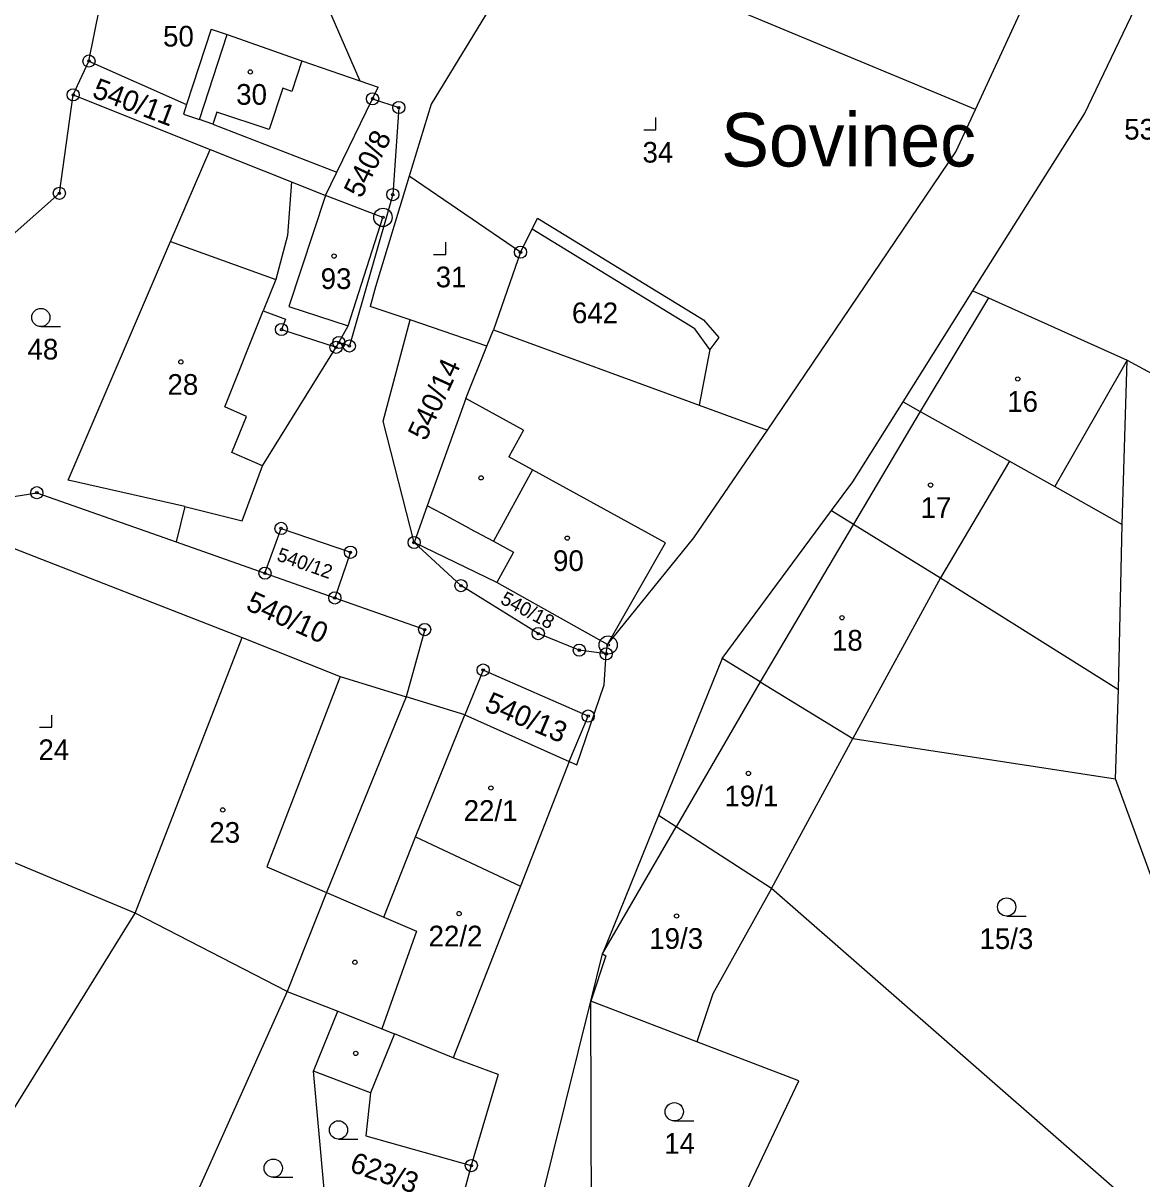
# Model space of a CAD drawing. Extents: x -547623 to -538651, y -1096714 to -1086522.
# Drawn here: x -544855 to -544763.1, y -1094700.8 to -1094605.9 of the extents above; entities that cross this region are included whole.
import ezdxf

# ---------------------------------------------------------------- set-up
doc = ezdxf.new("R2010")
doc.units = 0
for name, color, linetype in [('Vrstva 1', 7, 'Continuous'), ('Vrstva 25', 7, 'Continuous'), ('Vrstva 30', 7, 'Continuous'), ('Vrstva 33', 7, 'Continuous'), ('Vrstva 50', 7, 'Continuous'), ('Vrstva 83', 7, 'Continuous'), ('Vrstva 86', 7, 'Continuous'), ('Vrstva 90', 7, 'Continuous'), ('Vrstva 92', 7, 'Continuous')]:
    doc.layers.add(name, color=color, linetype=linetype)

msp = doc.modelspace()

# ---------------------------------------------------------------- linework, layer by layer
at = {"layer": 'Vrstva 1'}
for points in [[(-544767.78, -1094613.32), (-544755.08, -1094586.85)], [(-544812.58, -1094598.01), (-544821.44, -1094612.52)], [(-544782.68, -1094610.49), (-544812.58, -1094598.01)], [(-544776.73, -1094612.97), (-544769.76, -1094597.88)], [(-544849.55, -1094608.99), (-544847.75, -1094600.04)], [(-544830.34, -1094603.61), (-544827.31, -1094610.61)], [(-544839.52, -1094606.36), (-544841.53, -1094612.57)], [(-544839.52, -1094606.36), (-544838.2, -1094606.82)], [(-544838.2, -1094606.82), (-544832.05, -1094608.96)], [(-544850.84, -1094611.77), (-544849.55, -1094608.99)], [(-544849.55, -1094608.99), (-544841.53, -1094612.57)], [(-544832.05, -1094608.96), (-544827.31, -1094610.61)], [(-544827.31, -1094610.61), (-544825.79, -1094611.14)], [(-544776.73, -1094612.97), (-544782.68, -1094610.49)], [(-544851.98, -1094619.85), (-544850.84, -1094611.77)], [(-544850.84, -1094611.77), (-544839.6, -1094616.25)], [(-544826.25, -1094612.09), (-544825.79, -1094611.14)], [(-544841.53, -1094612.57), (-544841.78, -1094613.34)], [(-544829.18, -1094618.11), (-544826.25, -1094612.09)], [(-544826.25, -1094612.09), (-544824.1, -1094612.81)], [(-544824.1, -1094612.81), (-544824.59, -1094619.96)], [(-544821.44, -1094612.52), (-544823.25, -1094618.45)], [(-544841.78, -1094613.34), (-544840.46, -1094613.8)], [(-544839.37, -1094614.17), (-544840.46, -1094613.8)], [(-544778.33, -1094616.44), (-544776.73, -1094612.97)], [(-544776.93, -1094627.86), (-544767.78, -1094613.32)], [(-544839.37, -1094614.17), (-544829.18, -1094618.11)], [(-544842.85, -1094623.81), (-544839.6, -1094616.25)], [(-544839.6, -1094616.25), (-544832.92, -1094618.91)], [(-544793.8, -1094639.31), (-544778.33, -1094616.44)], [(-544830.11, -1094620.03), (-544829.18, -1094618.11)], [(-544823.25, -1094618.45), (-544826.02, -1094627.54)], [(-544814.1, -1094624.69), (-544823.25, -1094618.45)], [(-544832.92, -1094618.91), (-544833.25, -1094623.32)], [(-544832.92, -1094618.91), (-544830.11, -1094620.03)], [(-544855.87, -1094623.28), (-544851.98, -1094619.85)], [(-544825.41, -1094621.84), (-544830.11, -1094620.03)], [(-544824.59, -1094619.96), (-544828.16, -1094632.39)], [(-544828.26, -1094630.73), (-544825.41, -1094621.84)], [(-544813.15, -1094622.79), (-544812.7, -1094621.89)], [(-544812.7, -1094621.89), (-544799.08, -1094630.24)], [(-544833.25, -1094623.32), (-544834.19, -1094626.93)], [(-544814.1, -1094624.69), (-544813.15, -1094622.79)], [(-544851.26, -1094643.41), (-544842.85, -1094623.81)], [(-544814.1, -1094624.69), (-544816.33, -1094631.06)], [(-544834.19, -1094626.93), (-544835.23, -1094629.51)], [(-544826.02, -1094627.54), (-544826.46, -1094629.16)], [(-544782.67, -1094636.98), (-544776.93, -1094627.86)], [(-544776.93, -1094627.86), (-544775.66, -1094628.43)], [(-544775.66, -1094628.43), (-544764.27, -1094633.56)], [(-544835.23, -1094629.51), (-544833.4, -1094630.2)], [(-544823.17, -1094630.25), (-544826.46, -1094629.16)], [(-544833.4, -1094630.2), (-544833.73, -1094631.04)], [(-544829.02, -1094632.11), (-544828.26, -1094630.73)], [(-544825.38, -1094638.57), (-544823.17, -1094630.25)], [(-544816.87, -1094632.4), (-544823.17, -1094630.25)], [(-544799.08, -1094630.24), (-544797.82, -1094631.68)], [(-544833.73, -1094631.04), (-544829.25, -1094632.5)], [(-544816.87, -1094632.4), (-544816.33, -1094631.06)], [(-544816.33, -1094631.06), (-544799.42, -1094637.25)], [(-544797.82, -1094631.68), (-544798.55, -1094632.67)], [(-544835.29, -1094642.23), (-544829.25, -1094632.5)], [(-544829.25, -1094632.5), (-544829.02, -1094632.11)], [(-544828.16, -1094632.39), (-544829.02, -1094632.11)], [(-544818.6, -1094636.69), (-544816.87, -1094632.4)], [(-544798.55, -1094632.67), (-544799.42, -1094637.25)], [(-544764.67, -1094647.05), (-544764.27, -1094633.56)], [(-544764.27, -1094633.56), (-544756.99, -1094637.51)], [(-544818.6, -1094636.69), (-544821.76, -1094645.51)], [(-544799.42, -1094637.25), (-544793.8, -1094639.31)], [(-544786.81, -1094643.54), (-544782.67, -1094636.98)], [(-544782.67, -1094636.98), (-544781.27, -1094637.76)], [(-544781.27, -1094637.76), (-544773.94, -1094641.86)], [(-544822.84, -1094648.53), (-544825.38, -1094638.57)], [(-544799.86, -1094648.14), (-544793.8, -1094639.31)], [(-544836.95, -1094646.74), (-544835.29, -1094642.23)], [(-544773.94, -1094641.86), (-544770.22, -1094643.94)], [(-544841.68, -1094645.57), (-544851.26, -1094643.41)], [(-544788.56, -1094645.91), (-544786.81, -1094643.54)], [(-544770.22, -1094643.94), (-544764.67, -1094647.05)], [(-544857.98, -1094645.11), (-544853.83, -1094644.44)], [(-544853.83, -1094644.44), (-544842.38, -1094648.48)], [(-544841.68, -1094645.57), (-544842.38, -1094648.48)], [(-544841.68, -1094645.57), (-544836.95, -1094646.74)], [(-544821.76, -1094645.51), (-544822.84, -1094648.53)], [(-544797.54, -1094658.05), (-544788.56, -1094645.91)], [(-544788.56, -1094645.91), (-544786.74, -1094647.03)], [(-544786.74, -1094647.03), (-544779.59, -1094651.43)], [(-544764.98, -1094660.59), (-544764.67, -1094647.05)], [(-544835.09, -1094651.05), (-544833.77, -1094647.37)], [(-544833.77, -1094647.37), (-544828.07, -1094649.33)], [(-544856.31, -1094648.77), (-544836.96, -1094656.32)], [(-544842.38, -1094648.48), (-544835.09, -1094651.05)], [(-544818.99, -1094652.07), (-544822.84, -1094648.53)], [(-544816.05, -1094651.81), (-544822.84, -1094648.53)], [(-544806.94, -1094656.91), (-544799.86, -1094648.14)], [(-544828.07, -1094649.33), (-544829.35, -1094653.08)], [(-544835.09, -1094651.05), (-544829.35, -1094653.08)], [(-544806.94, -1094656.91), (-544816.05, -1094651.81)], [(-544779.59, -1094651.43), (-544764.98, -1094660.59)], [(-544812.64, -1094656.01), (-544818.99, -1094652.07)], [(-544829.35, -1094653.08), (-544821.97, -1094655.68)], [(-544845.75, -1094678.98), (-544836.96, -1094656.32)], [(-544836.96, -1094656.32), (-544828.92, -1094659.53)], [(-544821.97, -1094655.68), (-544823.49, -1094661.19)], [(-544809.27, -1094657.37), (-544812.64, -1094656.01)], [(-544807.06, -1094657.67), (-544809.27, -1094657.37)], [(-544807.06, -1094657.67), (-544806.94, -1094656.91)], [(-544807.24, -1094660.23), (-544807.06, -1094657.67)], [(-544797.54, -1094658.05), (-544802.77, -1094670.95)], [(-544794.41, -1094659.97), (-544797.54, -1094658.05)], [(-544817.17, -1094659), (-544818.66, -1094662.69)], [(-544808.54, -1094662.78), (-544817.17, -1094659)], [(-544828.92, -1094659.53), (-544823.49, -1094661.19)], [(-544809.47, -1094666.78), (-544807.24, -1094660.23)], [(-544794.41, -1094659.97), (-544786.8, -1094664.63)], [(-544823.49, -1094661.19), (-544830.03, -1094677.28)], [(-544818.66, -1094662.69), (-544823.49, -1094661.19)], [(-544765.21, -1094667.93), (-544764.98, -1094660.59)], [(-544818.66, -1094662.69), (-544810.09, -1094666.51)], [(-544810.09, -1094666.51), (-544808.54, -1094662.78)], [(-544793.49, -1094676.93), (-544786.8, -1094664.63)], [(-544786.8, -1094664.63), (-544765.21, -1094667.93)], [(-544810.09, -1094666.51), (-544814.1, -1094676.75)], [(-544810.09, -1094666.51), (-544809.47, -1094666.78)], [(-544761.84, -1094677.22), (-544765.21, -1094667.93)], [(-544802.77, -1094670.95), (-544807.37, -1094682.31)], [(-544801.32, -1094671.88), (-544802.77, -1094670.95)], [(-544845.75, -1094678.98), (-544862.15, -1094672.13)], [(-544825.33, -1094679.3), (-544822.72, -1094672.7)], [(-544822.72, -1094672.7), (-544814.1, -1094676.75)], [(-544793.49, -1094676.93), (-544801.32, -1094671.88)], [(-544830.03, -1094677.28), (-544833.26, -1094685.41)], [(-544814.1, -1094676.75), (-544819.62, -1094690.84)], [(-544793.49, -1094676.93), (-544798.3, -1094685.58)], [(-544761.16, -1094705.2), (-544793.49, -1094676.93)], [(-544856.17, -1094695.74), (-544845.75, -1094678.98)], [(-544833.26, -1094685.41), (-544845.75, -1094678.98)], [(-544825.33, -1094679.3), (-544822.64, -1094680.45)], [(-544822.64, -1094680.45), (-544825.48, -1094688.48)], [(-544808.31, -1094686.2), (-544807.37, -1094682.31)], [(-544833.26, -1094685.41), (-544841.88, -1094704.64)], [(-544833.26, -1094685.41), (-544829.11, -1094687.02)], [(-544798.3, -1094685.58), (-544799.62, -1094689.53)], [(-544813.52, -1094707.15), (-544808.31, -1094686.2)], [(-544799.62, -1094689.53), (-544808.31, -1094686.2)], [(-544808.27, -1094704.24), (-544808.31, -1094686.2)], [(-544831.1, -1094691.95), (-544829.11, -1094687.02)], [(-544829.11, -1094687.02), (-544825.48, -1094688.48)], [(-544791.23, -1094692.75), (-544799.62, -1094689.53)], [(-544815.93, -1094692.21), (-544819.62, -1094690.84)], [(-544826.41, -1094693.73), (-544831.1, -1094691.95)], [(-544830.24, -1094701.64), (-544831.1, -1094691.95)], [(-544815.93, -1094692.21), (-544818.14, -1094699.7)], [(-544797.96, -1094706.94), (-544791.23, -1094692.75)], [(-544826.41, -1094693.73), (-544826.81, -1094697.26)], [(-544826.81, -1094697.26), (-544818.14, -1094699.7)], [(-544818.14, -1094699.7), (-544819.59, -1094705.06)]]:
    msp.add_lwpolyline(points, dxfattribs=at)
at = {"layer": 'Vrstva 25'}
for p, q in [((-544853.5, -1094630.8), (-544851.9, -1094630.8)), ((-544774.16, -1094679.21), (-544772.56, -1094679.21)), ((-544801.47, -1094696.03), (-544799.87, -1094696.03)), ((-544829.05, -1094697.52), (-544827.45, -1094697.52)), ((-544834.41, -1094700.66), (-544832.81, -1094700.66))]:
    msp.add_line(p, q, dxfattribs=at)
for points in [[(-544803.98, -1094614.63), (-544802.98, -1094614.63), (-544802.98, -1094613.63)], [(-544821.24, -1094624.87), (-544820.24, -1094624.87), (-544820.24, -1094623.87)], [(-544853.6, -1094663.7), (-544852.6, -1094663.7), (-544852.6, -1094662.7)]]:
    msp.add_lwpolyline(points, dxfattribs=at)
for centre, radius in [((-544836.29, -1094609.88), 0.175), ((-544829.41, -1094625.01), 0.175), ((-544853.5, -1094630.05), 0.75), ((-544842, -1094633.7), 0.175), ((-544773.25, -1094635.1), 0.175), ((-544817.34, -1094643.22), 0.175), ((-544780.41, -1094643.81), 0.175), ((-544810.26, -1094648.17), 0.175), ((-544787.69, -1094654.71), 0.175), ((-544795.38, -1094667.49), 0.175), ((-544816.53, -1094668.69), 0.175), ((-544838.56, -1094670.49), 0.175), ((-544774.16, -1094678.46), 0.75), ((-544819.14, -1094679), 0.175), ((-544801.28, -1094679.2), 0.175), ((-544827.7, -1094683), 0.175), ((-544827.63, -1094690.49), 0.175), ((-544801.47, -1094695.28), 0.75), ((-544829.05, -1094696.77), 0.75), ((-544834.41, -1094699.91), 0.75)]:
    msp.add_circle(centre, radius, dxfattribs=at)
at = {"layer": 'Vrstva 30'}
for points in [[(-544813.15, -1094622.79), (-544812.7, -1094621.89)], [(-544812.7, -1094621.89), (-544799.08, -1094630.24)], [(-544799.78, -1094630.98), (-544813.15, -1094622.79)], [(-544799.08, -1094630.24), (-544797.82, -1094631.68)], [(-544798.55, -1094632.67), (-544799.78, -1094630.98)], [(-544797.82, -1094631.68), (-544798.55, -1094632.67)]]:
    msp.add_lwpolyline(points, dxfattribs=at)
at = {"layer": 'Vrstva 33'}
for points in [[(-544840.46, -1094613.8), (-544838.2, -1094606.82)], [(-544832.05, -1094608.96), (-544832.87, -1094611.48)], [(-544833.62, -1094611.23), (-544834.74, -1094614.62)], [(-544832.87, -1094611.48), (-544833.62, -1094611.23)], [(-544839.05, -1094613.18), (-544839.37, -1094614.17)], [(-544834.74, -1094614.62), (-544839.05, -1094613.18)], [(-544830.11, -1094620.03), (-544833.13, -1094629.14)], [(-544842.85, -1094623.81), (-544834.19, -1094626.93)], [(-544775.66, -1094628.43), (-544781.27, -1094637.76)], [(-544838.4, -1094637.39), (-544835.23, -1094629.51)], [(-544833.13, -1094629.14), (-544828.26, -1094630.73)], [(-544764.27, -1094633.56), (-544770.22, -1094643.94)], [(-544836.61, -1094638.17), (-544838.4, -1094637.39)], [(-544813.86, -1094639.3), (-544818.6, -1094636.69)], [(-544837.8, -1094641.14), (-544836.61, -1094638.17)], [(-544781.27, -1094637.76), (-544786.74, -1094647.03)], [(-544813.86, -1094639.3), (-544815.06, -1094641.49)], [(-544835.29, -1094642.23), (-544837.8, -1094641.14)], [(-544813.12, -1094642.56), (-544815.06, -1094641.49)], [(-544773.94, -1094641.86), (-544779.59, -1094651.43)], [(-544813.12, -1094642.56), (-544816.33, -1094648.42)], [(-544802.2, -1094648.56), (-544813.12, -1094642.56)], [(-544820.5, -1094646.18), (-544821.76, -1094645.51)], [(-544818.28, -1094647.37), (-544820.5, -1094646.18)], [(-544786.74, -1094647.03), (-544794.41, -1094659.97)], [(-544818.28, -1094647.37), (-544816.33, -1094648.42)], [(-544816.33, -1094648.42), (-544814.68, -1094649.31)], [(-544806.94, -1094656.91), (-544802.2, -1094648.56)], [(-544814.68, -1094649.31), (-544816.05, -1094651.81)], [(-544779.59, -1094651.43), (-544786.8, -1094664.63)], [(-544828.92, -1094659.53), (-544834.95, -1094675.17)], [(-544794.41, -1094659.97), (-544801.32, -1094671.88)], [(-544822.72, -1094672.7), (-544818.66, -1094662.69)], [(-544807.37, -1094682.31), (-544801.32, -1094671.88)], [(-544834.95, -1094675.17), (-544830.03, -1094677.28)], [(-544830.03, -1094677.28), (-544825.33, -1094679.3)], [(-544807.09, -1094682.47), (-544808.31, -1094686.2)], [(-544807.37, -1094682.31), (-544807.09, -1094682.47)], [(-544825.48, -1094688.48), (-544824.46, -1094688.89)], [(-544824.46, -1094688.89), (-544826.41, -1094693.73)], [(-544819.62, -1094690.84), (-544824.46, -1094688.89)]]:
    msp.add_lwpolyline(points, dxfattribs=at)
at = {"layer": 'Vrstva 83'}
for centre, radius in [((-544849.55, -1094608.99), 0.5), ((-544849.55, -1094608.99), 0.1), ((-544850.84, -1094611.77), 0.5), ((-544850.84, -1094611.77), 0.1), ((-544826.25, -1094612.09), 0.5), ((-544826.25, -1094612.09), 0.1), ((-544824.1, -1094612.81), 0.5), ((-544824.1, -1094612.81), 0.1), ((-544851.98, -1094619.85), 0.5), ((-544824.59, -1094619.96), 0.5), ((-544851.98, -1094619.85), 0.1), ((-544824.59, -1094619.96), 0.1), ((-544825.4, -1094621.83), 0.75), ((-544825.4, -1094621.83), 0.1), ((-544814.1, -1094624.69), 0.5), ((-544814.1, -1094624.69), 0.1), ((-544833.73, -1094631.04), 0.5), ((-544833.73, -1094631.04), 0.1), ((-544829.02, -1094632.11), 0.5), ((-544828.16, -1094632.39), 0.5), ((-544829.25, -1094632.5), 0.5), ((-544829.25, -1094632.5), 0.1), ((-544829.02, -1094632.11), 0.1), ((-544828.16, -1094632.39), 0.1), ((-544853.83, -1094644.44), 0.5), ((-544853.83, -1094644.44), 0.1), ((-544833.77, -1094647.37), 0.5), ((-544833.77, -1094647.37), 0.1), ((-544822.84, -1094648.53), 0.5), ((-544828.07, -1094649.33), 0.5), ((-544822.84, -1094648.53), 0.1), ((-544828.07, -1094649.33), 0.1), ((-544835.09, -1094651.05), 0.5), ((-544835.09, -1094651.05), 0.1), ((-544818.99, -1094652.07), 0.5), ((-544829.35, -1094653.08), 0.5), ((-544818.99, -1094652.07), 0.1), ((-544829.35, -1094653.08), 0.1), ((-544821.97, -1094655.68), 0.5), ((-544821.97, -1094655.68), 0.1), ((-544812.64, -1094656.01), 0.5), ((-544812.64, -1094656.01), 0.1), ((-544806.9, -1094656.95), 0.75), ((-544809.27, -1094657.37), 0.5), ((-544809.27, -1094657.37), 0.1), ((-544807.06, -1094657.67), 0.5), ((-544806.9, -1094656.95), 0.1), ((-544807.06, -1094657.67), 0.1), ((-544817.17, -1094659), 0.5), ((-544817.17, -1094659), 0.1), ((-544808.54, -1094662.78), 0.5), ((-544808.54, -1094662.78), 0.1), ((-544818.14, -1094699.7), 0.5), ((-544818.14, -1094699.7), 0.1)]:
    msp.add_circle(centre, radius, dxfattribs=at)
at = {"layer": 'Vrstva 90'}
for points in [[(-544840.46, -1094613.8), (-544838.2, -1094606.82)], [(-544838.2, -1094606.82), (-544832.05, -1094608.96)], [(-544832.05, -1094608.96), (-544832.87, -1094611.48)], [(-544833.62, -1094611.23), (-544834.74, -1094614.62)], [(-544832.87, -1094611.48), (-544833.62, -1094611.23)], [(-544839.37, -1094614.17), (-544840.46, -1094613.8)], [(-544839.05, -1094613.18), (-544839.37, -1094614.17)], [(-544834.74, -1094614.62), (-544839.05, -1094613.18)], [(-544830.11, -1094620.03), (-544833.13, -1094629.14)], [(-544825.41, -1094621.84), (-544830.11, -1094620.03)], [(-544828.26, -1094630.73), (-544825.41, -1094621.84)], [(-544851.26, -1094643.41), (-544842.85, -1094623.81)], [(-544842.85, -1094623.81), (-544834.19, -1094626.93)], [(-544834.19, -1094626.93), (-544835.23, -1094629.51)], [(-544775.66, -1094628.43), (-544781.27, -1094637.76)], [(-544775.66, -1094628.43), (-544764.27, -1094633.56)], [(-544838.4, -1094637.39), (-544835.23, -1094629.51)], [(-544833.13, -1094629.14), (-544828.26, -1094630.73)], [(-544764.27, -1094633.56), (-544770.22, -1094643.94)], [(-544836.61, -1094638.17), (-544838.4, -1094637.39)], [(-544837.8, -1094641.14), (-544836.61, -1094638.17)], [(-544781.27, -1094637.76), (-544786.74, -1094647.03)], [(-544781.27, -1094637.76), (-544773.94, -1094641.86)], [(-544781.27, -1094637.76), (-544773.94, -1094641.86)], [(-544835.29, -1094642.23), (-544837.8, -1094641.14)], [(-544836.95, -1094646.74), (-544835.29, -1094642.23)], [(-544773.94, -1094641.86), (-544779.59, -1094651.43)], [(-544773.94, -1094641.86), (-544770.22, -1094643.94)], [(-544813.12, -1094642.56), (-544816.33, -1094648.42)], [(-544802.2, -1094648.56), (-544813.12, -1094642.56)], [(-544841.68, -1094645.57), (-544851.26, -1094643.41)], [(-544841.68, -1094645.57), (-544836.95, -1094646.74)], [(-544786.74, -1094647.03), (-544794.41, -1094659.97)], [(-544786.74, -1094647.03), (-544779.59, -1094651.43)], [(-544786.74, -1094647.03), (-544779.59, -1094651.43)], [(-544816.33, -1094648.42), (-544814.68, -1094649.31)], [(-544806.94, -1094656.91), (-544802.2, -1094648.56)], [(-544814.68, -1094649.31), (-544816.05, -1094651.81)], [(-544806.94, -1094656.91), (-544816.05, -1094651.81)], [(-544779.59, -1094651.43), (-544786.8, -1094664.63)], [(-544845.75, -1094678.98), (-544836.96, -1094656.32)], [(-544836.96, -1094656.32), (-544828.92, -1094659.53)], [(-544828.92, -1094659.53), (-544834.95, -1094675.17)], [(-544794.41, -1094659.97), (-544801.32, -1094671.88)], [(-544794.41, -1094659.97), (-544786.8, -1094664.63)], [(-544794.41, -1094659.97), (-544786.8, -1094664.63)], [(-544822.72, -1094672.7), (-544818.66, -1094662.69)], [(-544818.66, -1094662.69), (-544810.09, -1094666.51)], [(-544793.49, -1094676.93), (-544786.8, -1094664.63)], [(-544810.09, -1094666.51), (-544814.1, -1094676.75)], [(-544825.33, -1094679.3), (-544822.72, -1094672.7)], [(-544822.72, -1094672.7), (-544814.1, -1094676.75)], [(-544822.72, -1094672.7), (-544814.1, -1094676.75)], [(-544807.37, -1094682.31), (-544801.32, -1094671.88)], [(-544793.49, -1094676.93), (-544801.32, -1094671.88)], [(-544793.49, -1094676.93), (-544801.32, -1094671.88)], [(-544834.95, -1094675.17), (-544830.03, -1094677.28)], [(-544830.03, -1094677.28), (-544833.26, -1094685.41)], [(-544814.1, -1094676.75), (-544819.62, -1094690.84)], [(-544793.49, -1094676.93), (-544798.3, -1094685.58)], [(-544833.26, -1094685.41), (-544845.75, -1094678.98)], [(-544825.33, -1094679.3), (-544822.64, -1094680.45)], [(-544822.64, -1094680.45), (-544825.48, -1094688.48)], [(-544807.09, -1094682.47), (-544808.31, -1094686.2)], [(-544807.37, -1094682.31), (-544807.09, -1094682.47)], [(-544798.3, -1094685.58), (-544799.62, -1094689.53)], [(-544799.62, -1094689.53), (-544808.31, -1094686.2)], [(-544825.48, -1094688.48), (-544824.46, -1094688.89)], [(-544819.62, -1094690.84), (-544824.46, -1094688.89)]]:
    msp.add_lwpolyline(points, dxfattribs=at)

# ---------------------------------------------------------------- texts
at = {"layer": 'Vrstva 50'}
msp.add_text('Sovinec', height=4.4, dxfattribs=at).set_placement((-544797.617, -1094617.65))
at = {"layer": 'Vrstva 86'}
for s, p in [('50', (-544843.463, -1094607.8)), ('539/1', (-544764.506, -1094615.44)), ('642', (-544809.873, -1094630.52)), ('48', (-544854.598, -1094633.5)), ('15/3', (-544776.397, -1094681.91)), ('14', (-544802.296, -1094698.73))]:
    msp.add_text(s, height=1.7, dxfattribs=at).set_placement(p)
for s, height, rotation, p in [('540/11', 1.7, 339.39882, (-544849.38, -1094611.932)), ('540/8', 1.7, 63.87084, (-544827.17, -1094620.336)), ('540/14', 1.7, 65.30733, (-544821.884, -1094640.265)), ('540/12', 1.14, 340.45596, (-544834.195, -1094649.982)), ('540/10', 1.7, 335.65563, (-544836.753, -1094654.009)), ('540/18', 1.14, 331.9848, (-544815.83, -1094653.491)), ('540/13', 1.7, 336.91347, (-544817.146, -1094662.299)), ('623/3', 1.7, 340.8039, (-544828.225, -1094700.15))]:
    msp.add_text(s, height=height, rotation=rotation, dxfattribs=at).set_placement(p)
at = {"layer": 'Vrstva 92'}
for s, p in [('30', (-544837.453, -1094612.58)), ('34', (-544804.078, -1094617.33)), ('93', (-544830.514, -1094627.71)), ('31', (-544821.066, -1094627.57)), ('28', (-544843.098, -1094636.4)), ('16', (-544774.117, -1094637.8)), ('17', (-544781.236, -1094646.51)), ('90', (-544811.429, -1094650.87)), ('18', (-544788.516, -1094657.41)), ('24', (-544853.698, -1094666.4)), ('19/1', (-544797.35, -1094670.19)), ('22/1', (-544818.767, -1094671.39)), ('23', (-544839.658, -1094673.19)), ('22/2', (-544821.65, -1094681.7)), ('19/3', (-544803.523, -1094681.9))]:
    msp.add_text(s, height=1.7, dxfattribs=at).set_placement(p)

doc.saveas('drawing.dxf')
